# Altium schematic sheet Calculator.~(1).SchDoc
size A4; SheetNumber: 1; SheetTotal: 1
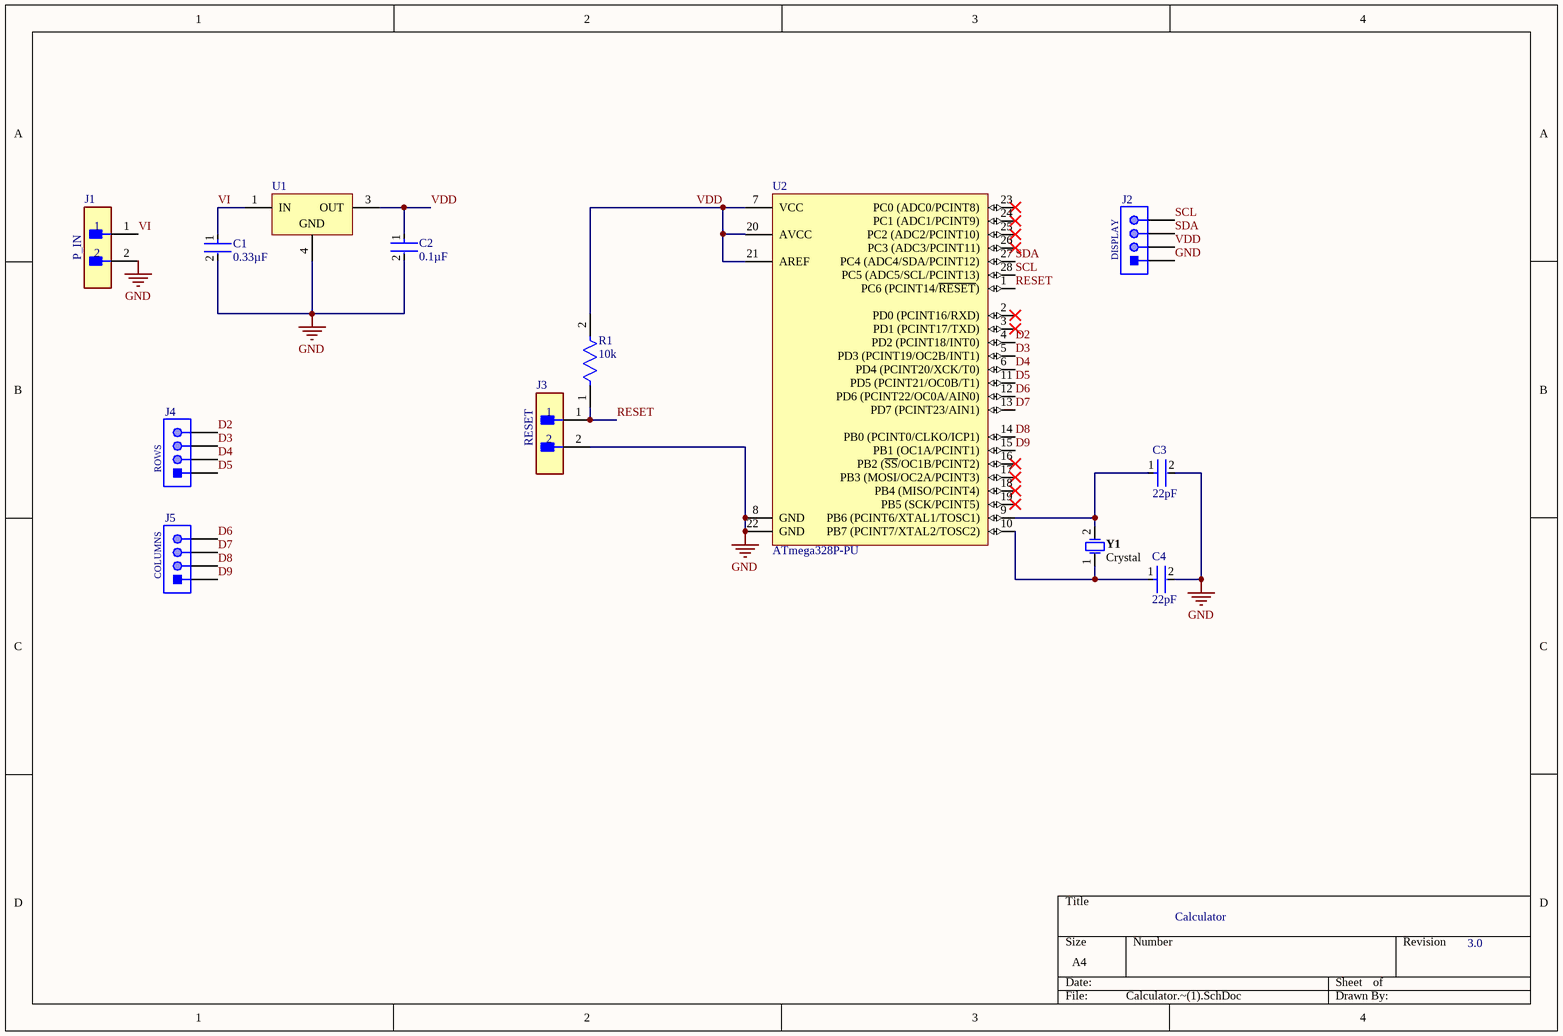
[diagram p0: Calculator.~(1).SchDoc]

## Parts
C1  0.33µF  [FP-RCE1K1-2_5-MFG]
C2  0.1µF  [FP-SR20-MFG]
C3  22pF  [FP-RCE0DB-MFG]
C4  22pF  [FP-RCE0DB-MFG]
J1  P_IN  [FP-M20-9990246-MFG]
J2  DISPLAY  [61900411121]
J3  RESET  [FP-M20-9990246-MFG]
J4  ROWS  [61900411121]
J5  COLUMNS  [61900411121]
R1  10k  [FP-MRS25-MFG]
U1  L7805CD2T-TR  [TO-263_M]  (value not drawn)
U2  ATmega328P-PU  [28P3]
Y1  Crystal  [FOX-FOXSLF160-20]

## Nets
GND: C1.2 C2.2 C3.2 C4.2 J1.2 J2.1 J3.2 U1.4(GND) U2.8(GND) U2.22(GND)
D2: J4.4 U2.4(PD2_(PCINT18/INT0))
D3: J4.3 U2.5(PD3_(PCINT19/OC2B/INT1))
D4: J4.2 U2.6(PD4_(PCINT20/XCK/T0))
D5: J4.1 U2.11(PD5_(PCINT21/OC0B/T1))
D6: J5.4 U2.12(PD6_(PCINT22/OC0A/AIN0))
D7: J5.3 U2.13(PD7_(PCINT23/AIN1))
D8: J5.2 U2.14(PB0_(PCINT0/CLKO/ICP1))
D9: J5.1 U2.15(PB1_(OC1A/PCINT1))
RESET: J3.1 R1.1 U2.1(PC6_(PCINT14/~{RESET}))
SCL: J2.4 U2.28(PC5_(ADC5/SCL/PCINT13))
SDA: J2.3 U2.27(PC4_(ADC4/SDA/PCINT12))
VDD: C2.1 J2.2 R1.2 U1.3(OUT) U2.7(VCC) U2.20(AVCC) U2.21(AREF)
VI: C1.1 J1.1 U1.1(IN)
NetC3_1: C3.1 U2.9(PB6_(PCINT6/XTAL1/TOSC1)) Y1.2
NetC4_1: C4.1 U2.10(PB7_(PCINT7/XTAL2/TOSC2)) Y1.1

Not connected (* = marked no-connect by the designer): U2 2(PD0_(PCINT16/RXD))* 3(PD1_(PCINT17/TXD))* 16(PB2_(~{SS}/OC1B/PCINT2))* 17(PB3_(MOSI/OC2A/PCINT3))* 18(PB4_(MISO/PCINT4))* 19(PB5_(SCK/PCINT5))* 23(PC0_(ADC0/PCINT8))* 24(PC1_(ADC1/PCINT9))* 25(PC2_(ADC2/PCINT10))* 26(PC3_(ADC3/PCINT11))*

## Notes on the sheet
- Calculator
- 3.0

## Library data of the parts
C1 = CMP-06035-005774-1: Cap Ceramic Monolithic 330nF 50V 10% Thru-Hole Bulk; Lead/Base Style: Formed Leads; Lead Diameter: 0.5mm; Dielectric: X7R
C2 = CMP-04427-000013-1: CAP CER 0.1UF 50V X7R RADIAL; Manufacturer Part Number: SR205C104KAR; Manufacturer: AVX; Material: Ceramic; Tolerance: 10%; Capacitance: 100nF; Value: 100nF
C3 C4 = CMP-06035-057691-1: Cap Ceramic 22pF 50V C0G ±5% Radial 2.5mm +125°C Ammo Pack; Lead Diameter: 0.5mm; Lead/Base Style: Straight
J1 J3 = CMP-15831-000009-1: CONN HEADER VERT 2POS 2.54MM; Manufacturer: Harwin; Manufacturer Part Number: M20-9990246; Conn Gender: Male; Conn Orientation: Vertical; Number Of Contacts: 2; Current Rating: 3A
J2 J4 J5 = CMP-1502-00586-1: Male Locking Header WR-WTB, THT, Vertical, pitch 2.54 mm, 1 x 4 position; Manufacturer: Wurth Elektronik; Working Voltage: 250VAC; Pitch: 2.54mm; Contact Resistance: 20mOhm; Position: 1x4
R1 = CMP-02408-000051-1: RES 1K OHM 0.6W 1% AXIAL; Power Rating: 600mW; Lead Diameter: 0.6mm; Voltage Rating (DC): 350V; Resistance: 1kR; Temperature Coefficient: 50ppm/°C
U1 = CMP-0244-00213-1: Positive Voltage Regulator, 3-Pin D2PAK, Tape and Reel
U2 = CMP-0095-00013-2: 8-bit AVR Microcontroller, 32KB Flash, 1KB EEPROM, 2KB SRAM, 28-pin PDIP, Industrial Grade (-40°C to 85°C)
Y1 = CMP-1749-00003-1: Resistance Weld Thru-Hole Crystal, 16 MHz, -20 to 70 degC, 2-Pin THD, RoHS, Bulk; Voltage Rating: 250 V; Tolerance: 1%; Resistance: 221 kohm; Case\Package: Axial; Power Rating: 250 mW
